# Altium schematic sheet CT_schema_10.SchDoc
size 405 x 220 mm
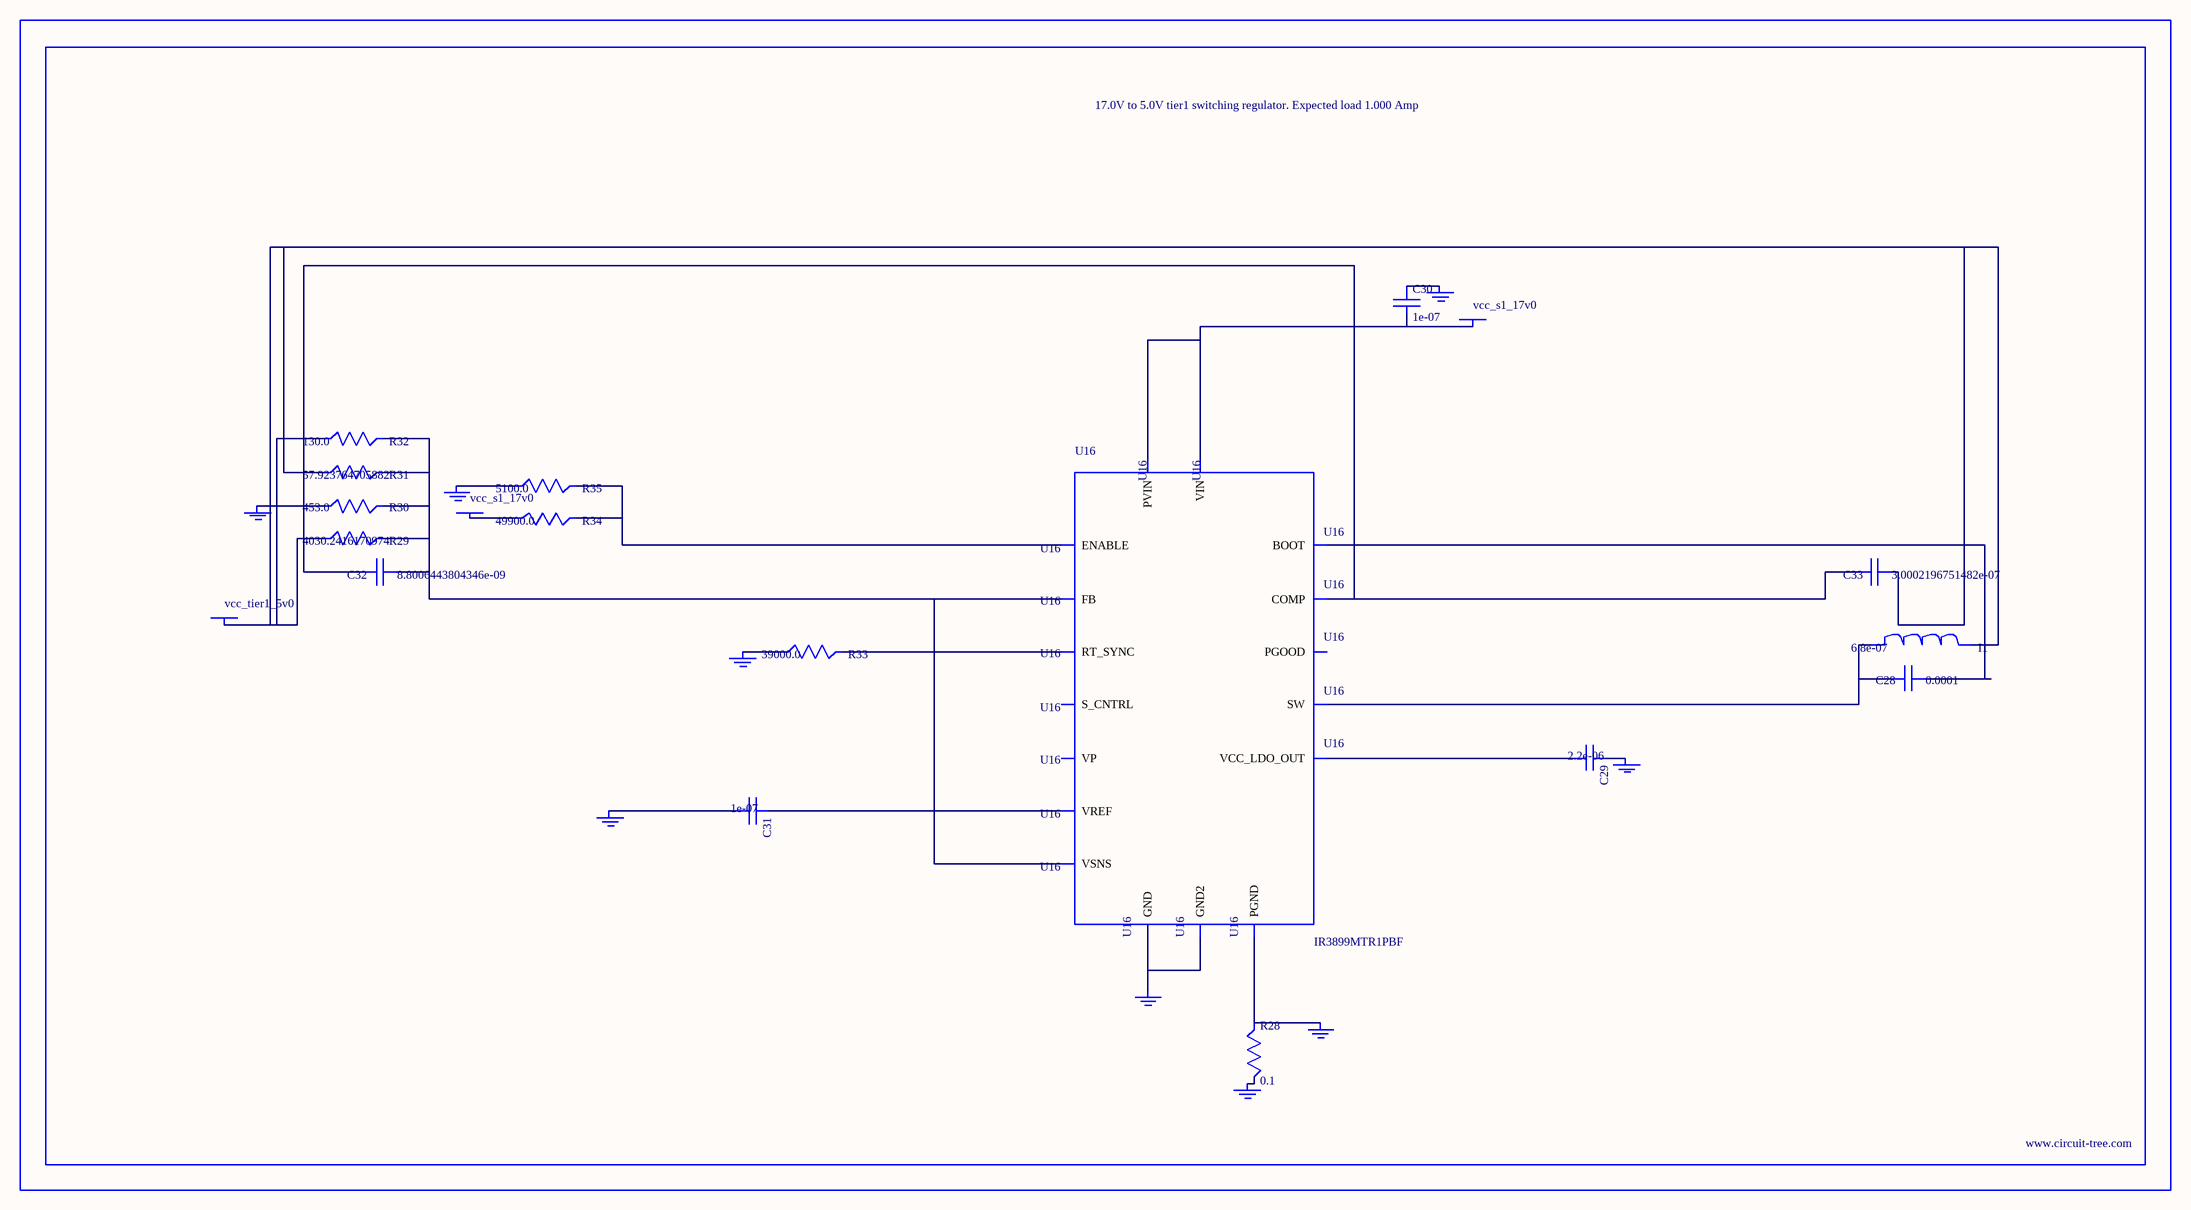
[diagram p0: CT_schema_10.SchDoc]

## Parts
BORDER9  (no value)
C28  0.0001  [C1210]
C29  2.2e-06  [C0603]
C30  1e-07  [C0402]
C31  1e-07  [C0402]
C32  8.8006443804346e-09  [R0603]
C33  3.0002196751482e-07  [R0603]
GND_INSTANCE_9_0  (no value)
GND_INSTANCE_9_1  (no value)
GND_INSTANCE_9_2  (no value)
GND_INSTANCE_9_3  (no value)
GND_INSTANCE_9_4  (no value)
GND_INSTANCE_9_5  (no value)
GND_INSTANCE_9_6  (no value)
GND_INSTANCE_9_7  (no value)
GND_INSTANCE_9_8  (no value)
I1  6.8e-07  [IND25X25CZ]
POWER_INSTANCE_9_0  vcc_s1_17v0
POWER_INSTANCE_9_1  vcc_s1_17v0
POWER_INSTANCE_9_2  vcc_tier1_5v0
R28  0.1  [R0603]
R29  4030.2416170974  [R0603]
R30  453.0  [R0603]
R31  57.923764705882  [R0603]
R32  130.0  [R0603]
R33  39000.0  [R0603]
R34  49900.0  [R0603]
R35  5100.0  [R0603]
U16  IR3899MTR1PBF  [IR3899MTR1PBF]

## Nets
NetC28_1: C28.1 U16.14(BOOT)
NetC28_2: C28.2 I1.1 U16.12(SW)
NetC29_1: C29.1 GND_INSTANCE_9_4.0(GND)
NetC29_2: C29.2 U16.10(VCC_LDO_OUT)
NetC30_1: C30.1 GND_INSTANCE_9_3.0(GND)
NetC30_2: C30.2 POWER_INSTANCE_9_0.0(PWR) U16.9(VIN) U16.13(PVIN)
NetC31_1: C31.1 U16.2(VREF)
NetC31_2: C31.2 GND_INSTANCE_9_1.0(GND)
NetC32_1: C32.1 R29.2 R30.2 R31.2 R32.2 U16.1(FB) U16.8(VSNS)
NetC32_2: C32.2 C33.2 U16.3(COMP)
NetC33_1: C33.1 I1.2 POWER_INSTANCE_9_2.0(PWR) R29.1 R31.1 R32.1
NetGND_INSTANCE_9_0_0: GND_INSTANCE_9_0.0(GND) R30.1
NetGND_INSTANCE_9_2_0: GND_INSTANCE_9_2.0(GND) R33.1
NetGND_INSTANCE_9_5_0: GND_INSTANCE_9_5.0(GND) R28.2
NetGND_INSTANCE_9_6_0: GND_INSTANCE_9_6.0(GND) R28.1 U16.11(PGND)
NetGND_INSTANCE_9_7_0: GND_INSTANCE_9_7.0(GND) R35.1
NetGND_INSTANCE_9_8_0: GND_INSTANCE_9_8.0(GND) U16.4(GND) U16.17(GND2)
NetPOWER_INSTANCE_9_1_0: POWER_INSTANCE_9_1.0(PWR) R34.1
NetR33_2: R33.2 U16.5(RT_SYNC)
NetR34_2: R34.2 R35.2 U16.15(ENABLE)

Not connected (* = marked no-connect by the designer): U16 6(S_CNTRL) 7(PGOOD) 16(VP)

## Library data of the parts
BORDER9 = BORDER_PAGE9
C28 = GRM32ER61A107ME20L
C29 = C0603C225K8RACTU
C30 C31 = C0402C104K3RACTU
C32 = C32
C33 = C33
GND_INSTANCE_9_0-GND_INSTANCE_9_8 = GND
I1 = IHLP2525CZERR68M01
POWER_INSTANCE_9_0-POWER_INSTANCE_9_2 = PWR
R28 = ERJ-3RSFR10V
R29 = R29
R30 = ERJ-3EKF4530V
R31 = R31
R32 = RC0603JR-07130RL
R33 = RC0603JR-0739KL
R34 = RC0603FR-0749K9
R35 = RC0603JR-075K1L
